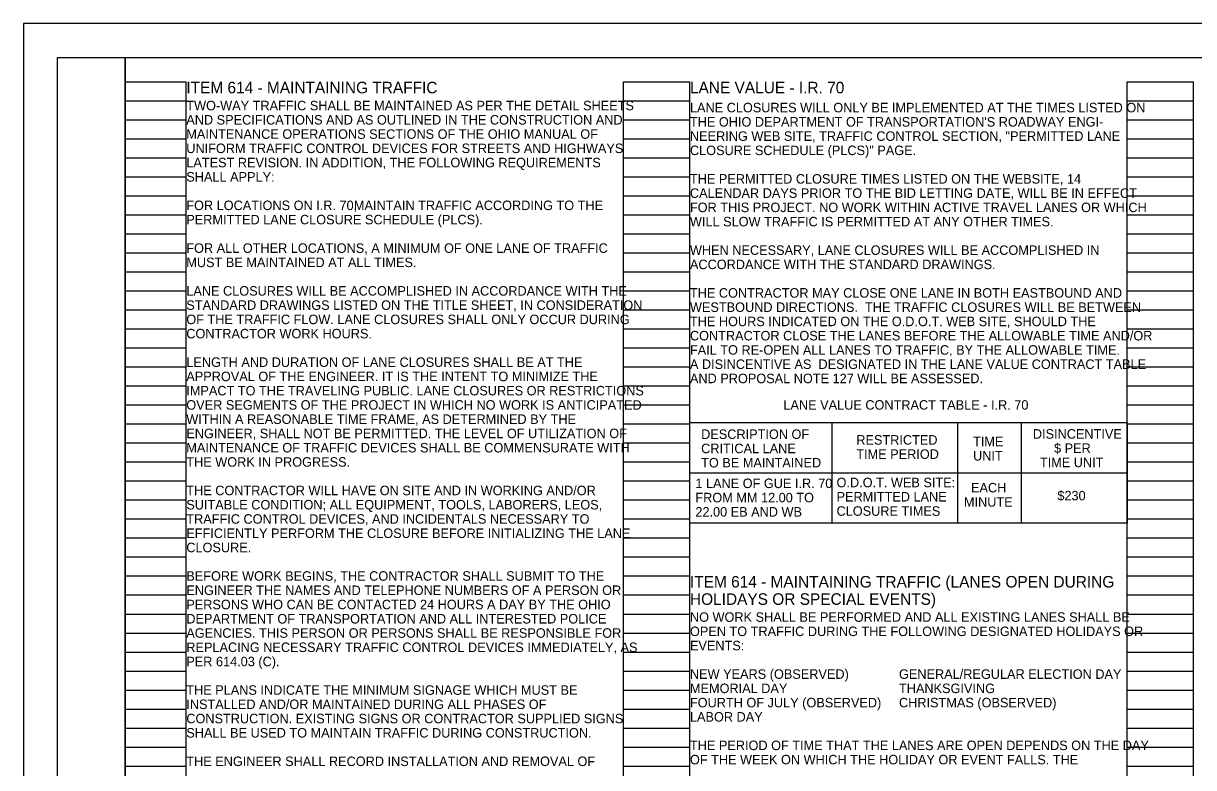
# Model space of a CAD drawing. Extents: x 0 to 34, y 0 to 22.
# Drawn here: x 0 to 17.24, y 11.04 to 22 of the extents above; entities that cross this region are included whole.
import ezdxf

# ---------------------------------------------------------------- set-up
doc = ezdxf.new("R2010")
doc.units = 0
for name, color, linetype in [('SH_Border', 7, 'Continuous'), ('SH_Cut_Line', 7, 'Continuous'), ('SH_Data', 7, 'Continuous'), ('SH_Text', 7, 'Continuous')]:
    doc.layers.add(name, color=color, linetype=linetype)

msp = doc.modelspace()

# ---------------------------------------------------------------- linework, layer by layer
at = {"layer": 'SH_Border'}
for points in [[(0.5, 21.5), (1.5, 21.5), (1.5, 0.5), (0.5, 0.5)], [(1.5, 21.5), (33.5, 21.5), (33.5, 0.5), (1.5, 0.5)]]:
    msp.add_lwpolyline(points, close=True, dxfattribs=at)
at = {"layer": 'SH_Cut_Line'}
msp.add_lwpolyline([(0, 0), (34, 0), (34, 22), (0, 22)], close=True, dxfattribs=at)
at = {"layer": 'SH_Data'}
for p, q in [((1.5, 0.98), (1.5, 21.14)), ((1.5, 21.14), (2.4, 21.14)), ((2.4, 0.98), (2.4, 21.14)), ((8.84, 0.98), (8.84, 21.14)), ((8.84, 21.14), (9.82, 21.14)), ((9.82, 0.98), (9.82, 21.14)), ((16.26, 0.98), (16.26, 21.14)), ((16.26, 21.14), (17.24, 21.14)), ((17.24, 0.98), (17.24, 21.14)), ((1.5, 20.86), (2.4, 20.86)), ((8.84, 20.86), (9.82, 20.86)), ((16.26, 20.86), (17.24, 20.86)), ((1.5, 20.58), (2.4, 20.58)), ((8.84, 20.58), (9.82, 20.58)), ((16.26, 20.58), (17.24, 20.58)), ((1.5, 20.3), (2.4, 20.3)), ((8.84, 20.3), (9.82, 20.3)), ((16.26, 20.3), (17.24, 20.3)), ((1.5, 20.02), (2.4, 20.02)), ((8.84, 20.02), (9.82, 20.02)), ((16.26, 20.02), (17.24, 20.02)), ((1.5, 19.74), (2.4, 19.74)), ((8.84, 19.74), (9.82, 19.74)), ((16.26, 19.74), (17.24, 19.74)), ((1.5, 19.46), (2.4, 19.46)), ((8.84, 19.46), (9.82, 19.46)), ((16.26, 19.46), (17.24, 19.46)), ((1.5, 19.18), (2.4, 19.18)), ((8.84, 19.18), (9.82, 19.18)), ((16.26, 19.18), (17.24, 19.18)), ((1.5, 18.9), (2.4, 18.9)), ((8.84, 18.9), (9.82, 18.9)), ((16.26, 18.9), (17.24, 18.9)), ((1.5, 18.62), (2.4, 18.62)), ((8.84, 18.62), (9.82, 18.62)), ((16.26, 18.62), (17.24, 18.62)), ((1.5, 18.34), (2.4, 18.34)), ((8.84, 18.34), (9.82, 18.34)), ((16.26, 18.34), (17.24, 18.34)), ((1.5, 18.06), (2.4, 18.06)), ((8.84, 18.06), (9.82, 18.06)), ((16.26, 18.06), (17.24, 18.06)), ((1.5, 17.78), (2.4, 17.78)), ((8.84, 17.78), (9.82, 17.78)), ((16.26, 17.78), (17.24, 17.78)), ((1.5, 17.5), (2.4, 17.5)), ((8.84, 17.5), (9.82, 17.5)), ((16.26, 17.5), (17.24, 17.5)), ((1.5, 17.22), (2.4, 17.22)), ((8.84, 17.22), (9.82, 17.22)), ((16.26, 17.22), (17.24, 17.22)), ((1.5, 16.94), (2.4, 16.94)), ((8.84, 16.94), (9.82, 16.94)), ((16.26, 16.94), (17.24, 16.94)), ((1.5, 16.66), (2.4, 16.66)), ((8.84, 16.66), (9.82, 16.66)), ((16.26, 16.66), (17.24, 16.66)), ((1.5, 16.38), (2.4, 16.38)), ((8.84, 16.38), (9.82, 16.38)), ((16.26, 16.38), (17.24, 16.38)), ((1.5, 16.1), (2.4, 16.1)), ((8.84, 16.1), (9.82, 16.1)), ((16.26, 16.1), (17.24, 16.1)), ((1.5, 15.82), (2.4, 15.82)), ((8.84, 15.82), (9.82, 15.82)), ((16.26, 15.82), (17.24, 15.82)), ((1.5, 15.54), (2.4, 15.54)), ((8.84, 15.54), (9.82, 15.54)), ((16.26, 15.54), (17.24, 15.54)), ((1.5, 15.26), (2.4, 15.26)), ((8.84, 15.26), (9.82, 15.26)), ((16.26, 15.26), (17.24, 15.26)), ((1.5, 14.98), (2.4, 14.98)), ((8.84, 14.98), (9.82, 14.98)), ((16.26, 14.98), (17.24, 14.98)), ((1.5, 14.7), (2.4, 14.7)), ((8.84, 14.7), (9.82, 14.7)), ((16.26, 14.7), (17.24, 14.7)), ((1.5, 14.42), (2.4, 14.42)), ((8.84, 14.42), (9.82, 14.42)), ((16.26, 14.42), (17.24, 14.42)), ((1.5, 14.14), (2.4, 14.14)), ((8.84, 14.14), (9.82, 14.14)), ((16.26, 14.14), (17.24, 14.14)), ((1.5, 13.86), (2.4, 13.86)), ((8.84, 13.86), (9.82, 13.86)), ((16.26, 13.86), (17.24, 13.86)), ((1.5, 13.58), (2.4, 13.58)), ((8.84, 13.58), (9.82, 13.58)), ((16.26, 13.58), (17.24, 13.58)), ((1.5, 13.3), (2.4, 13.3)), ((8.84, 13.3), (9.82, 13.3)), ((16.26, 13.3), (17.24, 13.3)), ((1.5, 13.02), (2.4, 13.02)), ((8.84, 13.02), (9.82, 13.02)), ((16.26, 13.02), (17.24, 13.02)), ((1.5, 12.74), (2.4, 12.74)), ((8.84, 12.74), (9.82, 12.74)), ((16.26, 12.74), (17.24, 12.74)), ((1.5, 12.46), (2.4, 12.46)), ((8.84, 12.46), (9.82, 12.46)), ((16.26, 12.46), (17.24, 12.46)), ((1.5, 12.18), (2.4, 12.18)), ((8.84, 12.18), (9.82, 12.18)), ((16.26, 12.18), (17.24, 12.18)), ((1.5, 11.9), (2.4, 11.9)), ((8.84, 11.9), (9.82, 11.9)), ((16.26, 11.9), (17.24, 11.9)), ((1.5, 11.62), (2.4, 11.62)), ((8.84, 11.62), (9.82, 11.62)), ((16.26, 11.62), (17.24, 11.62)), ((1.5, 11.34), (2.4, 11.34)), ((8.84, 11.34), (9.82, 11.34)), ((16.26, 11.34), (17.24, 11.34)), ((1.5, 11.06), (2.4, 11.06)), ((8.84, 11.06), (9.82, 11.06)), ((16.26, 11.06), (17.24, 11.06))]:
    msp.add_line(p, q, dxfattribs=at)
at = {"layer": 'SH_Text'}
for p, q in [((11.914, 14.636), (11.914, 16.12)), ((13.766, 14.636), (13.766, 16.12)), ((14.705, 14.636), (14.705, 16.12)), ((9.82, 15.382), (16.26, 15.382))]:
    msp.add_line(p, q, dxfattribs=at)
msp.add_lwpolyline([(9.82, 16.12), (16.26, 16.12), (16.26, 14.636), (9.82, 14.636)], close=True, dxfattribs=at)

# ---------------------------------------------------------------- texts
for s, height, p in [('ITEM 614 - MAINTAINING TRAFFIC', 0.17, (2.4, 20.97)), ('LANE VALUE - I.R. 70', 0.17, (9.82, 20.97)), ('TWO-WAY TRAFFIC SHALL BE MAINTAINED AS PER THE DETAIL SHEETS ', 0.14, (2.4, 20.72)), ('LANE CLOSURES WILL ONLY BE IMPLEMENTED AT THE TIMES LISTED ON ', 0.14, (9.82, 20.69)), ('AND SPECIFICATIONS AND AS OUTLINED IN THE CONSTRUCTION AND ', 0.14, (2.4, 20.51)), ("THE OHIO DEPARTMENT OF TRANSPORTATION'S ROADWAY ENGI-", 0.14, (9.82, 20.48)), ('MAINTENANCE OPERATIONS SECTIONS OF THE OHIO MANUAL OF ', 0.14, (2.4, 20.3)), ('NEERING WEB SITE, TRAFFIC CONTROL SECTION, "PERMITTED LANE ', 0.14, (9.82, 20.27)), ('UNIFORM TRAFFIC CONTROL DEVICES FOR STREETS AND HIGHWAYS ', 0.14, (2.4, 20.09)), ('CLOSURE SCHEDULE (PLCS)" PAGE.', 0.14, (9.82, 20.06)), ('LATEST REVISION. IN ADDITION, THE FOLLOWING REQUIREMENTS ', 0.14, (2.4, 19.88)), ('SHALL APPLY:', 0.14, (2.4, 19.67)), ('THE PERMITTED CLOSURE TIMES LISTED ON THE WEBSITE, 14 ', 0.14, (9.82, 19.64)), ('CALENDAR DAYS PRIOR TO THE BID LETTING DATE, WILL BE IN EFFECT ', 0.14, (9.82, 19.43)), ('FOR LOCATIONS ON I.R. 70, ', 0.14, (2.4, 19.25)), ('MAINTAIN TRAFFIC ACCORDING TO THE ', 0.14, (4.869, 19.25)), ('FOR THIS PROJECT. NO WORK WITHIN ACTIVE TRAVEL LANES OR WHICH ', 0.14, (9.82, 19.22)), ('PERMITTED LANE CLOSURE SCHEDULE (PLCS).', 0.14, (2.4, 19.04)), ('WILL SLOW TRAFFIC IS PERMITTED AT ANY OTHER TIMES.', 0.14, (9.82, 19.01)), ('FOR ALL OTHER LOCATIONS, A MINIMUM OF ONE LANE OF TRAFFIC ', 0.14, (2.4, 18.62)), ('WHEN NECESSARY, LANE CLOSURES WILL BE ACCOMPLISHED IN ', 0.14, (9.82, 18.59)), ('MUST BE MAINTAINED AT ALL TIMES.', 0.14, (2.4, 18.41)), ('ACCORDANCE WITH THE STANDARD DRAWINGS.  ', 0.14, (9.82, 18.38)), ('LANE CLOSURES WILL BE ACCOMPLISHED IN ACCORDANCE WITH THE ', 0.14, (2.4, 17.99)), ('THE CONTRACTOR MAY CLOSE ONE LANE IN BOTH EASTBOUND AND', 0.14, (9.82, 17.96)), ('STANDARD DRAWINGS LISTED ON THE TITLE SHEET, IN CONSIDERATION ', 0.14, (2.4, 17.78)), ('WESTBOUND DIRECTIONS.  THE TRAFFIC CLOSURES WILL BE BETWEEN', 0.14, (9.82, 17.75)), ('OF THE TRAFFIC FLOW. LANE CLOSURES SHALL ONLY OCCUR DURING ', 0.14, (2.4, 17.57)), ('THE HOURS INDICATED ON THE O.D.O.T. WEB SITE, SHOULD THE', 0.14, (9.82, 17.54)), ('CONTRACTOR WORK HOURS.', 0.14, (2.4, 17.36)), ('CONTRACTOR CLOSE THE LANES BEFORE THE ALLOWABLE TIME AND/OR', 0.14, (9.82, 17.33)), ('FAIL TO RE-OPEN ALL LANES TO TRAFFIC, BY THE ALLOWABLE TIME.', 0.14, (9.82, 17.12)), ('LENGTH AND DURATION OF LANE CLOSURES SHALL BE AT THE ', 0.14, (2.4, 16.94)), ('A DISINCENTIVE AS  DESIGNATED IN THE LANE VALUE CONTRACT TABLE', 0.14, (9.82, 16.91)), ('APPROVAL OF THE ENGINEER. IT IS THE INTENT TO MINIMIZE THE ', 0.14, (2.4, 16.73)), ('AND PROPOSAL NOTE 127 WILL BE ASSESSED.  ', 0.14, (9.82, 16.7)), ('IMPACT TO THE TRAVELING PUBLIC. LANE CLOSURES OR RESTRICTIONS ', 0.14, (2.4, 16.52)), ('OVER SEGMENTS OF THE PROJECT IN WHICH NO WORK IS ANTICIPATED', 0.14, (2.4, 16.31)), ('LANE VALUE CONTRACT TABLE - I.R. 70', 0.14, (11.197, 16.31)), ('WITHIN A REASONABLE TIME FRAME, AS DETERMINED BY THE ', 0.14, (2.4, 16.1)), ('ENGINEER, SHALL NOT BE PERMITTED. THE LEVEL OF UTILIZATION OF ', 0.14, (2.4, 15.89)), ('DESCRIPTION OF ', 0.14, (9.985, 15.879)), ('RESTRICTED ', 0.14, (12.271, 15.795)), ('TIME ', 0.14, (13.991, 15.771)), ('DISINCENTIVE', 0.14, (14.872, 15.883)), ('MAINTENANCE OF TRAFFIC DEVICES SHALL BE COMMENSURATE WITH ', 0.14, (2.4, 15.68)), ('CRITICAL LANE', 0.14, (9.985, 15.669)), ('TIME PERIOD', 0.14, (12.271, 15.585)), ('UNIT', 0.14, (13.991, 15.561)), ('      $ PER ', 0.14, (14.872, 15.673)), ('THE WORK IN PROGRESS.', 0.14, (2.4, 15.47)), ('TO BE MAINTAINED', 0.14, (9.985, 15.459)), ('  TIME UNIT', 0.14, (14.872, 15.463)), ('THE CONTRACTOR WILL HAVE ON SITE AND IN WORKING AND/OR ', 0.14, (2.4, 15.05)), ('1 LANE OF GUE I.R. 70', 0.14, (9.9, 15.155)), ('O.D.O.T. WEB SITE:', 0.14, (11.98, 15.167)), ('  EACH', 0.14, (13.857, 15.091)), ('FROM MM 12.00 TO ', 0.14, (9.9, 14.945)), ('PERMITTED LANE ', 0.14, (11.98, 14.957)), ('MINUTE', 0.14, (13.857, 14.881)), ('$230', 0.14, (15.233, 14.974)), ('SUITABLE CONDITION; ALL EQUIPMENT, TOOLS, LABORERS, LEOS, ', 0.14, (2.4, 14.84)), ('22.00 EB AND WB', 0.14, (9.9, 14.735)), ('CLOSURE TIMES', 0.14, (11.98, 14.747)), ('TRAFFIC CONTROL DEVICES, AND INCIDENTALS NECESSARY TO ', 0.14, (2.4, 14.63)), ('EFFICIENTLY PERFORM THE CLOSURE BEFORE INITIALIZING THE LANE ', 0.14, (2.4, 14.42)), ('CLOSURE.', 0.14, (2.4, 14.21)), ('BEFORE WORK BEGINS, THE CONTRACTOR SHALL SUBMIT TO THE ', 0.14, (2.4, 13.79)), ('ITEM 614 - MAINTAINING TRAFFIC (LANES OPEN DURING ', 0.17, (9.82, 13.69)), ('ENGINEER THE NAMES AND TELEPHONE NUMBERS OF A PERSON OR ', 0.14, (2.4, 13.58)), ('PERSONS WHO CAN BE CONTACTED 24 HOURS A DAY BY THE OHIO ', 0.14, (2.4, 13.37)), ('HOLIDAYS OR SPECIAL EVENTS)', 0.17, (9.82, 13.435)), ('DEPARTMENT OF TRANSPORTATION AND ALL INTERESTED POLICE ', 0.14, (2.4, 13.16)), ('NO WORK SHALL BE PERFORMED AND ALL EXISTING LANES SHALL BE ', 0.14, (9.82, 13.185)), ('OPEN TO TRAFFIC DURING THE FOLLOWING DESIGNATED HOLIDAYS OR ', 0.14, (9.82, 12.975)), ('AGENCIES. THIS PERSON OR PERSONS SHALL BE RESPONSIBLE FOR ', 0.14, (2.4, 12.95)), ('REPLACING NECESSARY TRAFFIC CONTROL DEVICES IMMEDIATELY, AS ', 0.14, (2.4, 12.74)), ('EVENTS:', 0.14, (9.82, 12.765)), ('PER 614.03 (C).', 0.14, (2.4, 12.53)), ('NEW YEARS (OBSERVED) ', 0.14, (9.82, 12.345)), ('GENERAL/REGULAR ELECTION DAY', 0.14, (12.9, 12.345)), ('THE PLANS INDICATE THE MINIMUM SIGNAGE WHICH MUST BE ', 0.14, (2.4, 12.11)), ('MEMORIAL DAY', 0.14, (9.82, 12.135)), ('THANKSGIVING', 0.14, (12.9, 12.135)), ('FOURTH OF JULY (OBSERVED)', 0.14, (9.82, 11.925)), ('CHRISTMAS (OBSERVED)', 0.14, (12.9, 11.925)), ('INSTALLED AND/OR MAINTAINED DURING ALL PHASES OF ', 0.14, (2.4, 11.9)), ('CONSTRUCTION. EXISTING SIGNS OR CONTRACTOR SUPPLIED SIGNS ', 0.14, (2.4, 11.69)), ('LABOR DAY', 0.14, (9.82, 11.715)), ('SHALL BE USED TO MAINTAIN TRAFFIC DURING CONSTRUCTION.', 0.14, (2.4, 11.48)), ('THE PERIOD OF TIME THAT THE LANES ARE OPEN DEPENDS ON THE DAY ', 0.14, (9.82, 11.295)), ('OF THE WEEK ON WHICH THE HOLIDAY OR EVENT FALLS. THE ', 0.14, (9.82, 11.085)), ('THE ENGINEER SHALL RECORD INSTALLATION AND REMOVAL OF ', 0.14, (2.4, 11.06))]:
    msp.add_text(s, height=height, dxfattribs=at).set_placement(p)

doc.saveas('drawing.dxf')
